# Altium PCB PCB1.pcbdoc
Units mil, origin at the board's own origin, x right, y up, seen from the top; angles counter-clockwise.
Board outline 17715 x 7065 mil, 4 copper layers (Top Layer, Inner1, Inner2, Bottom Layer); 91 components, 117 nets, 364 pads, 110 vias.
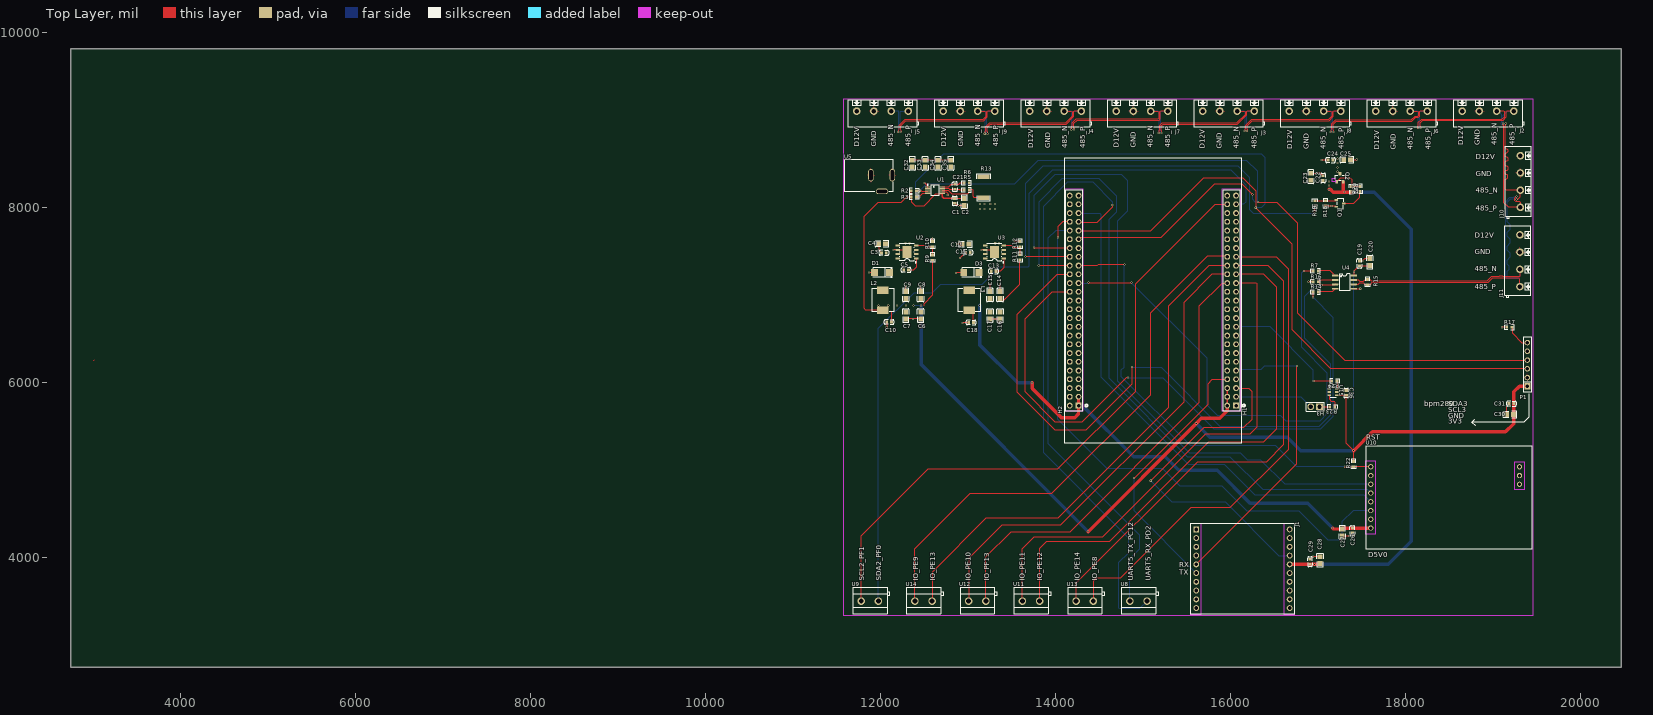
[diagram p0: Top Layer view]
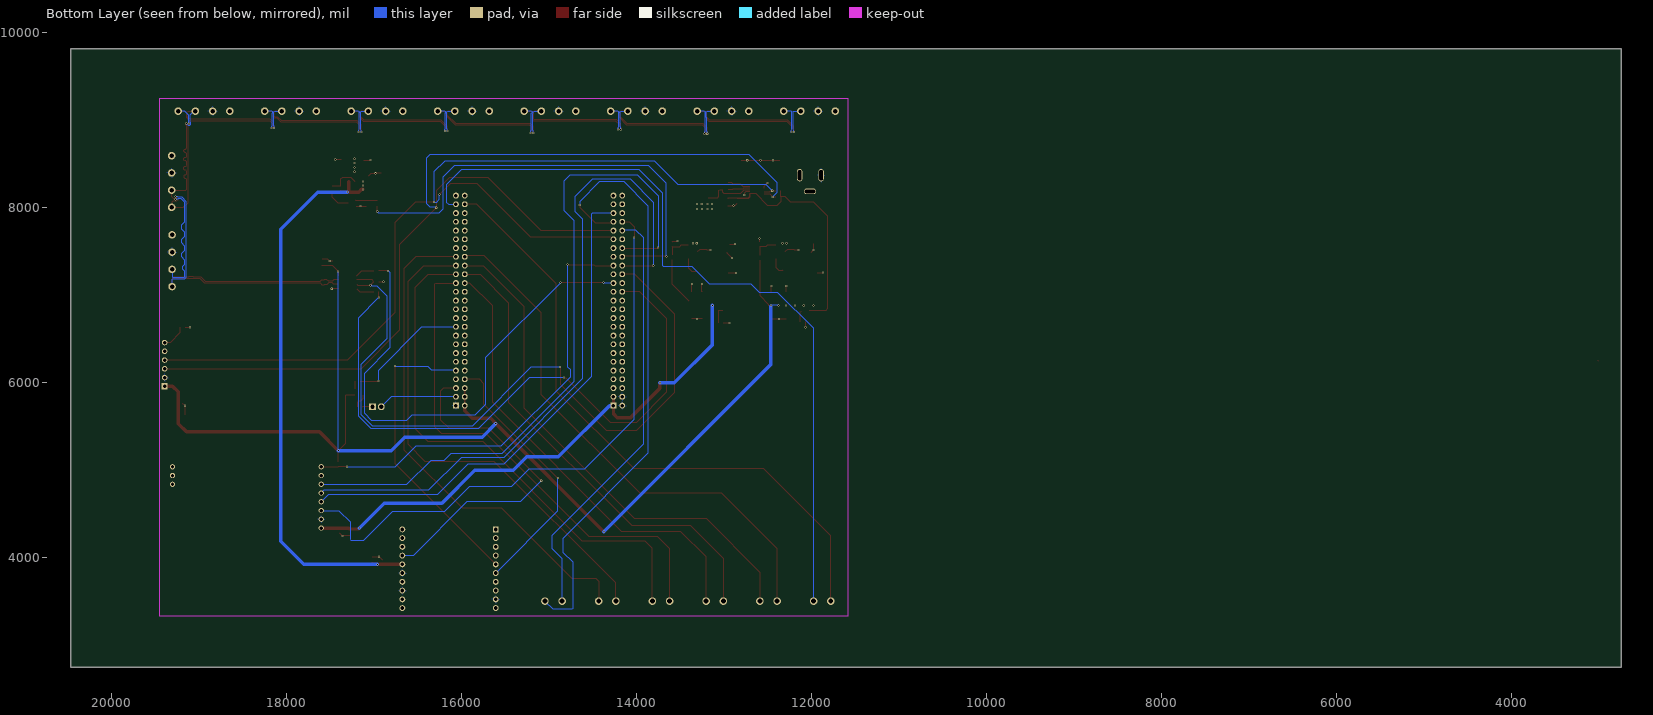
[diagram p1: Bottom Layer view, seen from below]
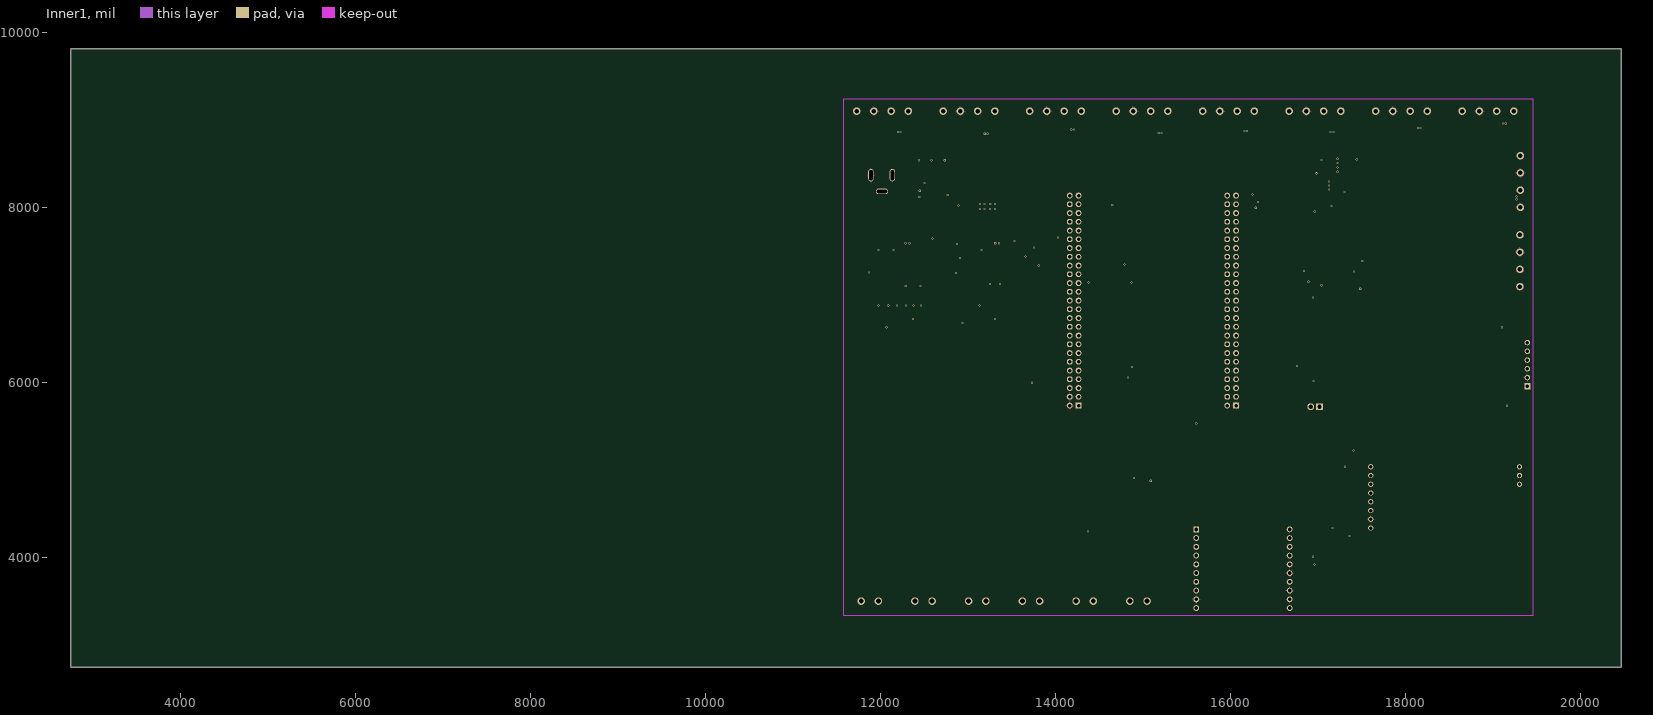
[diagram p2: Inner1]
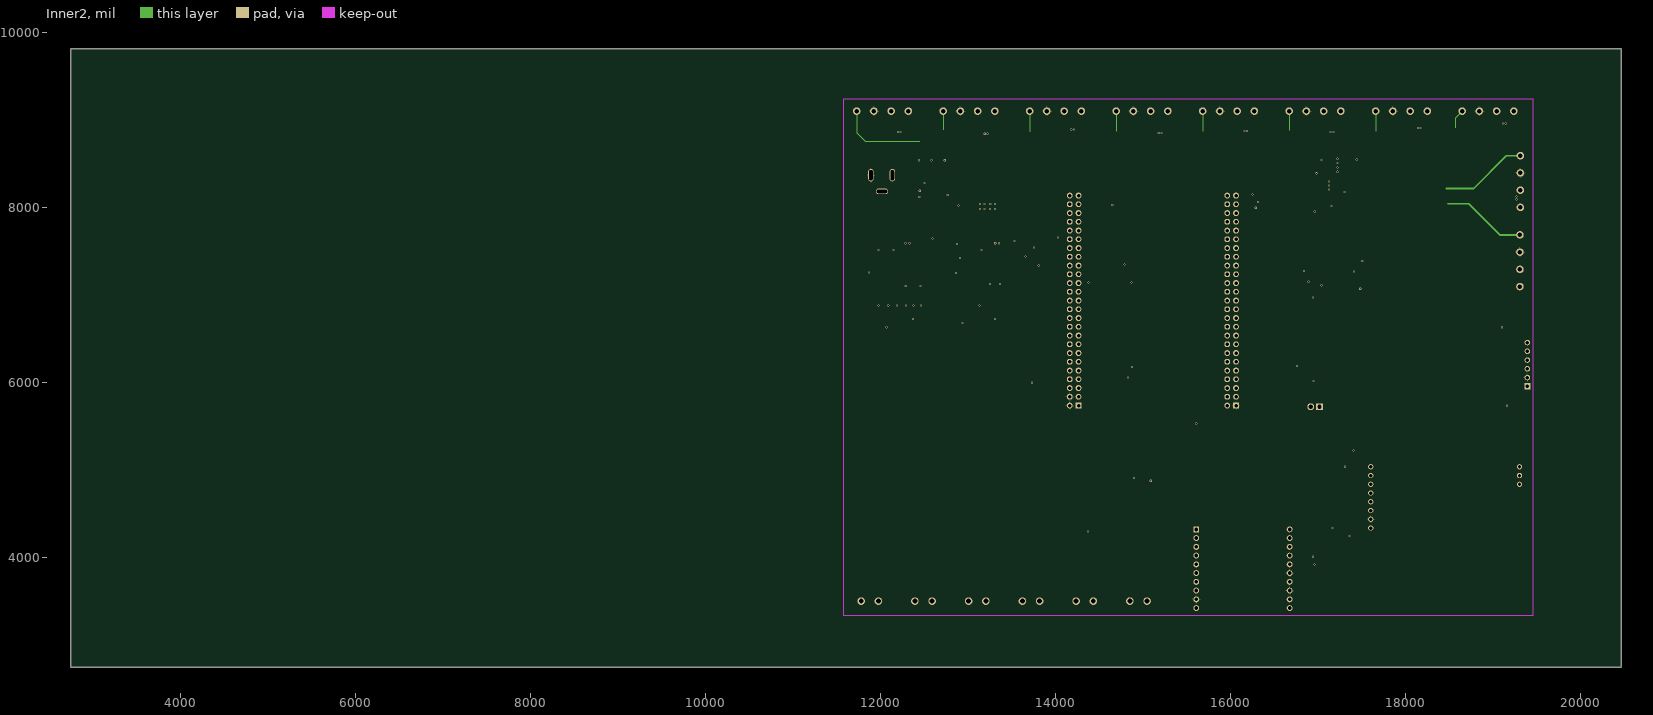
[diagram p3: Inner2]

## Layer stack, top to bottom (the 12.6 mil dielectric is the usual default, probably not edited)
Top Layer: signal copper (thickness not stored)
Dielectric: dielectric 12.6, FR-4, Dk 4.8
Inner1: signal copper (thickness not stored)
Dielectric: dielectric 12.6, FR-4, Dk 4.8
Inner2: signal copper (thickness not stored)
Dielectric: dielectric 12.6, FR-4, Dk 4.8
Bottom Layer: signal copper (thickness not stored)

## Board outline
20465,2750 2750,2750 2750,9815 20465,9815

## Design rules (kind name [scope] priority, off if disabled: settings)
BoardOutlineClearance copperThickness1oz [All] p0: genericclearance=10 ignorepadtopadclearanceinfootprint=FALSE except(0: Arc-SplitContinuation Track-SplitContinuation SMDPad-SplitContinuation THPad-SplitContinuation Via-SplitContinuation Fill-SplitContinuation Poly-SplitContinuation Region-SplitContinuation Text-SplitContinuation; 6: Track-CutoutEdge SMDPad-CutoutEdge THPad-CutoutEdge Via-CutoutEdge Region-CutoutEdge; 11.8: Track-OutlineEdge SMDPad-OutlineEdge THPad-OutlineEdge Via-OutlineEdge Fill-OutlineEdge Region-OutlineEdge Poly-OutlineEdge Text-OutlineEdge Fill-CutoutEdge)
BoardOutlineClearance copperThickness2oz [All] p0: genericclearance=10 ignorepadtopadclearanceinfootprint=FALSE except(0: Arc-SplitContinuation Track-SplitContinuation SMDPad-SplitContinuation THPad-SplitContinuation Via-SplitContinuation Fill-SplitContinuation Poly-SplitContinuation Region-SplitContinuation Text-SplitContinuation; 6: Track-CutoutEdge SMDPad-CutoutEdge THPad-CutoutEdge Via-CutoutEdge Region-CutoutEdge; 11.8: Track-OutlineEdge SMDPad-OutlineEdge THPad-OutlineEdge Via-OutlineEdge Fill-OutlineEdge Region-OutlineEdge Poly-OutlineEdge Text-OutlineEdge Fill-CutoutEdge)
Clearance copperThickness1oz [(InNet('D3V3') OR InNet('GND') OR InNet('D12V') OR InNet('$1N1879') OR InNet('$1N3397') OR InNet('$1N3226') OR InNet('$1N3388') OR InNet('D5V0') OR InNet('$1N488') OR InNet('$1N614') OR InNet('12VOUT') OR InNet('RESET') OR InNet('PA1') OR InNet('PC3') OR InNet('USART2_TX_PA2') OR InNet('USART2_RX_PA3') OR InNet('PC2') OR InNet('PA5') OR InNet('PA4') OR InNet('PC4') OR InNet('PA7') OR InNet('PB0') OR InNet('PC5') OR InNet('PB2') OR InNet('PB1') OR InNet('PF11') OR InNet('PF6') OR InNet('PF7') OR InNet('PB13') OR InNet('PB12') OR InNet('PD11') OR InNet('PF5') OR InNet('PD13') OR InNet('PD12') OR InNet('IO_PE11') OR InNet('IO_PF13') OR InNet('IO_PE12') OR InNet('IO_PE10') OR InNet('IO_PE14') OR InNet('IO_PE13') OR InNet('IO_PE8') OR InNet('IO_PE9') OR InNet('PD15') OR InNet('PE7') OR InNet('PD14') OR InNet('PE15') OR InNet('PD9') OR InNet('PD8') OR InNet('PF4') OR InNet('PD10') OR InNet('PF2') OR InNet('PF3') OR InNet('SDA2_PF0') OR InNet('SCL2_PF1') OR InNet('PB15') OR InNet('PF12') OR InNet('VBAT') OR InNet('PB4') OR InNet('PG14') OR InNet('PG13') OR InNet('PG12') OR InNet('PG11') OR InNet('PE3') OR InNet('PE2') OR InNet('PE5') OR InNet('PE6') OR InNet('PC0') OR InNet('PC1') OR InNet('PE1') OR InNet('PE0') OR InNet('PB7') OR InNet('PG10') OR InNet('PG9') OR InNet('PD5') OR InNet('PD4') OR InNet('PD3') OR InNet('PD1') OR InNet('PD0') OR InNet('PA15') OR InNet('USART3_TX_PB10') OR InNet('USART3_RX_PB11') OR InNet('PB3') OR InNet('PB5') OR InNet('EN_PB6') OR InNet('RST_PA6') OR InNet('AUX_PA12') OR InNet('PA11') OR InNet('EN_PG8') OR InNet('PG7') OR InNet('MD0_PG6') OR InNet('SDA3_PC9') OR InNet('PC8') OR InNet('SCL3_PA8') OR InNet('UART5_TX_PC12') OR InNet('UART5_RX_PD2') OR InNet('UART4_RX_PC11') OR InNet('UART4_TX_PC10') OR InNet('PG15') OR InNet('PD7') OR InNet('PD6') OR InNet('PC7') OR InNet('PC6') OR InNet('$1N7784') OR InNet('$1N8212') OR InNet('$1N8382') OR InNet('$1N8425') OR InNet('12VIN') OR InNet('$1N4237') OR InNet('$1N2426') OR InNet('$1N3228') OR InNet('$1N4276') OR InNet('485_1_N') OR InNet('485_1_P') OR InNet('TIM13_PF8') OR InNet('$1N39239') OR InNet('$1N39104') OR InNet('$1N39095'))] p1: gap=7 ignorepadtopadclearanceinfootprint=FALSE except(5.9: Track-Track; 6: Track-SMDPad SMDPad-SMDPad Track-THPad SMDPad-THPad THPad-THPad Track-Via SMDPad-Via THPad-Via Via-Via SMDPad-Fill THPad-Fill Via-Fill Fill-Fill Track-Region SMDPad-Region THPad-Region Via-Region Region-Region Track-Poly SMDPad-Poly THPad-Poly Via-Poly Fill-Poly Region-Poly Poly-Poly Track-Text SMDPad-Text THPad-Text Via-Text Fill-Text Region-Text Poly-Text Text-Text; 6.9: Track-Hole SMDPad-Hole THPad-Hole Via-Hole Fill-Hole Region-Hole Poly-Hole Text-Hole Sheet-Hole; 11.8: Track-Fill Fill-Region Track-Sheet SMDPad-Sheet THPad-Sheet Via-Sheet Fill-Sheet Region-Sheet Poly-Sheet Text-Sheet)
Clearance copperThickness2oz [All] p1: gap=7 ignorepadtopadclearanceinfootprint=FALSE except(6: Track-SMDPad SMDPad-SMDPad Track-THPad SMDPad-THPad THPad-THPad Track-Via SMDPad-Via THPad-Via Via-Via SMDPad-Fill THPad-Fill Via-Fill Fill-Fill Track-Region SMDPad-Region THPad-Region Via-Region Region-Region Track-Poly SMDPad-Poly THPad-Poly Via-Poly Fill-Poly Region-Poly Poly-Poly Track-Text SMDPad-Text THPad-Text Via-Text Fill-Text Region-Text Poly-Text Text-Text; 6.9: Track-Hole SMDPad-Hole THPad-Hole Via-Hole Fill-Hole Region-Hole Poly-Hole Text-Hole Sheet-Hole; 8: Track-Track; 11.8: Track-Fill Fill-Region Track-Sheet SMDPad-Sheet THPad-Sheet Via-Sheet Fill-Sheet Region-Sheet Poly-Sheet Text-Sheet)
DiffPairsRouting differentialPair [All] p1: maxuncoupledlength=10 minlimit=5.9843 maxlimit=5.9843 mostfreqgap=5.9843 toplayer_minwidth=5 toplayer_prefwidth=10 toplayer_maxwidth=100 bottomlayer_minwidth=5 bottomlayer_prefwidth=10 bottomlayer_maxwidth=100 midlayer1_minwidth=5 midlayer1_prefwidth=10 midlayer1_maxwidth=100 midlayer2_minwidth=5 midlayer2_prefwidth=10 midlayer2_maxwidth=100
PasteMaskExpansion pasteMaskExpansion [All] p1: expansion=0
PlaneConnect innerPlane [All] p1: planeconnectstyle=Relief reliefexpansion=20 reliefentries=4 reliefconductorwidth=10 reliefairgap=10
PolygonConnect copperRegion [All] p1: connectstyle=Direct reliefentries=4 reliefconductorwidth=10 polygonreliefangle="90 Angle" airgapwidth=10
RoutingVias viaSize [All] p1: viastyle="Through Hole" holewidth=12.0078 minholewidth=11.811 maxholewidth=248.0314 width=24.0158 minwidth=19.685 maxwidth=393.7008
SolderMaskExpansion solderMaskExpansion [All] p1: useseparateexpansions=TRUE expansion=2.0079 expansionbottom=2.0079
Width copperThickness1oz [All] p1: maxlimit=100 minlimit=5 preferedwidth=12
Width copperThickness2oz [All] p1: maxlimit=100 minlimit=8 preferedwidth=10

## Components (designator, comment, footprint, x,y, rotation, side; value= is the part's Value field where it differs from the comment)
C1 "CC0603KRX7R9BB104" C0603 12850,8080 r90 top
C2 "CL21A106KAYNNNE_C15850" C0805 12960,8065 r90 top
C3 "CC0603KRX7R9BB104" C0603 12040,7485 r0 top
C4 "CL21A106KAYNNNE_C15850" C0805 12020,7590 r0 top
C5 "0603B103K500NT" C0603 12295,7290 r0 top
C6 "CL21A106KAYNNNE_C15850" C0805 12460,6770 r270 top
C7 "CL21A106KAYNNNE_C15850" C0805 12290,6770 r270 top
C8 "CL21A106KAYNNNE_C15850" C0805 12460,7003.13 r90 top
C9 "CL21A106KAYNNNE_C15850" C0805 12290,7003.13 r90 top
C10 "CC0603KRX7R9BB104" C0603 12100,6695 r0 top
C11 "CC0603KRX7R9BB104" C0603 13000,7490 r0 top
C12 "CL21A106KAYNNNE_C15850" C0805 12975,7585 r0 top
C13 "0603B103K500NT" C0603 13295,7275 r0 top
C14 "CL21A106KAYNNNE_C15850" C0805 13368.29,7003.13 r90 top
C15 "CL21A106KAYNNNE_C15850" C0805 13252.64,7003.13 r90 top
C16 "CL21A106KAYNNNE_C15850" C0805 13368.29,6770 r270 top
C17 "CL21A106KAYNNNE_C15850" C0805 13252.64,6770 r270 top
C18 "CC0603KRX7R9BB104" C0603 13036.58,6688.76 r0 top
C19 "CC0603KRX7R9BB104" C0603 17475,7365 r270 top
C20 "CL21A106KAYNNNE_C15850" C0805 17595,7380 r270 top
C21 "CC0603KRX7R9BB104" C0603 12851.49,8241.02 r90 top
C22 "CC0603KRX7R9BB104" C0603 17060,8340 r90 top
C23 "CL21A106KAYNNNE_C15850" C0805 16920,8355 r90 top
C24 "CC0603KRX7R9BB104" C0603 17145,8545 r180 top
C25 "CL21A106KAYNNNE_C15850" C0805 17335,8550 r0 top
C26 "CC0603KRX7R9BB104" C0603 17395,4310 r90 top
C27 "CL21A106KAYNNNE_C15850" C0805 17280,4290 r90 top
C28 "CL21A106KAYNNNE_C15850" C0805 17024.79,3972.86 r270 top
C29 "CC0603KRX7R9BB104" C0603 16910,3955 r270 top
C30 "CL21A106KAYNNNE_C15850" C0805 19198.48,5637.1 r0 top
C31 "CC0603KRX7R9BB104" C0603 19213.48,5762.1 r0 top
C32 "CL21A106KAYNNNE_C15850" C0805 12364.68,8504.69 r90 top
C33 "CL21A106KAYNNNE_C15850" C0805 12511.45,8504.69 r90 top
C34 "CL21A106KAYNNNE_C15850" C0805 12658.23,8504.69 r90 top
C35 "CL21A106KAYNNNE_C15850" C0805 12805,8504.69 r90 top
C36 "CC0603KRX7R9BB104" C0603 17325,5885 r270 top
D1 "SS34_C8678" SMA_L4.3-W2.6-LS5.2-RD 12020,7260 r180 top
D3 "SS34_C8678" SMA_L4.3-W2.6-LS5.2-RD 13040,7260 r180 top
H1 "2.54-2*25P母" HDR-TH_50P-P2.54-V-F-R2-C25-S2.54-1 16015,6940 r90 top locked
H2 "2.54-2*25P母" HDR-TH_50P-P2.54-V-F-R2-C25-S2.54-1 14215,6940 r90 top locked
H3 "PZ254V-11-02P" HDR-TH_2P-P2.54-V-M 16969,5726.31 r180 top
J1 "EC800K核心板" HDR-TH_20P-P2.54-V-M-R2-C10-S2.54_HIF3H-20P-2.54W 15610,4325 r270 top
J2 "传感器端子" CONN-TH_4P-P5.00_KF301-5.0-4P 18945,9105 r180 top
J3 "传感器端子" CONN-TH_4P-P5.00_KF301-5.0-4P 15979.29,9105 r180 top
J4 "传感器端子" CONN-TH_4P-P5.00_KF301-5.0-4P 14002.14,9105 r180 top
J5 "传感器端子" CONN-TH_4P-P5.00_KF301-5.0-4P 12025,9105 r180 top
J6 "传感器端子" CONN-TH_4P-P5.00_KF301-5.0-4P 17956.43,9105 r180 top
J7 "传感器端子" CONN-TH_4P-P5.00_KF301-5.0-4P 14990.71,9105 r180 top
J8 "传感器端子" CONN-TH_4P-P5.00_KF301-5.0-4P 16967.86,9105 r180 top
J9 "传感器端子" CONN-TH_4P-P5.00_KF301-5.0-4P 13013.57,9105 r180 top
J10 "传感器端子" CONN-TH_4P-P5.00_KF301-5.0-4P 19315,8300 r90 top
J11 "传感器端子" CONN-TH_4P-P5.00_KF301-5.0-4P 19310,7395 r90 top
L2 "MWSA0603S-100MT" IND-SMD_L7.1-W6.6 12030,6945 r270 top
L3 "MWSA0603S-100MT" IND-SMD_L7.1-W6.6 13015,6945 r270 top
P1 "2.54-1*6P母" HDR-TH_6P-P2.54-V-F 19395,6210 r90 top
Q1 "S8050 J3Y(RANGE:200-350)" SOT-23-3_L3.0-W1.7-P0.95-LS2.9-BR 17255,8050 r180 top
Q2 "AO3401A_C15127" SOT-23_L2.9-W1.3-P1.90-LS2.4-BR 17252.93,8342.93 r270 top
R2 "0603WAF4701T5E" R0603 12382.84,8195 r180 top
R3 "0603WAF4701T5E" R0603 12382.84,8125 r180 top
R5 "0603WAF100JT5E" R0603 12985.34,8206.05 r0 top
R6 "0603WAF100JT5E" R0603 12985.34,8286.05 r0 top
R7 "0603WAF330JT5E" R0603 16975,7280 r0 top
R9 "0603WAF8201T5E" R0603 12595,7430 r90 top
R10 "0603WAF5101T5E" R0603 12595,7585 r90 top
R11 "0603WAF1202T5E" R0603 13595,7435 r90 top
R12 "0603WAF3901T5E" R0603 13595,7585 r90 top
R13 "JER2512F3R010" R2512 13180,8235 r270 top
R14 "0603WAF330JT5E" R0603 16975,7040 r0 top
R15 "0603WAF1200T5E" R0603 17570,7150 r90 top
R16 "0603WAF4701T5E" R0603 16975,7155 r0 top
R17 "0603WAF4701T5E" R0603 19190,6635 r0 top
R18 "0603WAF5101T5E" R0603 17090,8050 r90 top
R19 "0603WAF3901T5E" R0603 16965,8050 r270 top
R20 "0603WAF1004T5E" R0603 17480,8215 r90 top
R21 "0603WAF1004T5E" R0603 17385,8215 r270 top
R22 "0603WAF4701T5E" R0603 17410,5070 r90 top
R23 "0603WAF1200T5E" R0603 17165,5725 r180 top
R24 "0603WAF330JT5E" R0603 17190,6020 r180 top
U1 "INA226AIDGSR" MSOP-10_L3.0-W3.0-P0.50-LS5.0-BL 12625.34,8201.05 r270 top
U2 "TPS5430DDAR" ESOP-8_L4.9-W3.9-P1.27-LS6.0-TL-EP 12305,7495 r180 top
U3 "TPS5430DDAR" ESOP-8_L4.9-W3.9-P1.27-LS6.0-TL-EP 13305.01,7495 r180 top
U4 "SP3485EN-L/TR" SOIC-8_L5.0-W4.0-P1.27-LS6.0-BL 17305,7150 r270 top
U5 "XDJK-0051-025" DC-IN-TH_XDJK-0051-025 12015,8280 r0 top
U8 "KF301-5.0-2P" CONN-TH_P5.00_KF301-5.0-2P 14950,3505 r0 top
U9 "KF301-5.0-2P" CONN-TH_P5.00_KF301-5.0-2P 11879.47,3505 r0 top
U10 "LORA模块" LORA 17605,4340 r0 top
U11 "KF301-5.0-2P" CONN-TH_P5.00_KF301-5.0-2P 13721.79,3505 r0 top
U12 "KF301-5.0-2P" CONN-TH_P5.00_KF301-5.0-2P 13107.68,3505 r0 top
U13 "KF301-5.0-2P" CONN-TH_P5.00_KF301-5.0-2P 14335.89,3505 r0 top
U14 "KF301-5.0-2P" CONN-TH_P5.00_KF301-5.0-2P 12493.58,3505 r0 top
U15 "CN825S" SOT-23-6_L2.9-W1.6-P0.95-LS2.8-BL 17175,5895 r270 top

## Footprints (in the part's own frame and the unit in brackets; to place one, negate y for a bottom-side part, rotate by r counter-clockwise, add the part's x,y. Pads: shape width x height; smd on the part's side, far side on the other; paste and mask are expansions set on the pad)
C0603 [mm]
  rect 0.8x0.9 smd: 1(-0.7,0) 2(0.7,0)
  silkscreen extent -1.39,-0.71 1.39,0.71
C0805 [mm]
  rect 1.41x1.35 smd: 1(-1,0) 2(1,0)
  silkscreen extent -1.96,-0.9 1.96,0.9
CONN-TH_4P-P5.00_KF301-5.0-4P [mm]
  round 2.2 hole 1.3: 1(-7.5,0) 2(-2.5,0) 3(2.5,0) 4(7.5,0)
  silkscreen extent -10.58,-3.18 10.03,4.57
CONN-TH_P5.00_KF301-5.0-2P [mm]
  round 2.2 hole 1.4: 1(-2.5,0) 2(2.5,0)
  silkscreen extent -5,-3.7 5.71,4
DC-IN-TH_XDJK-0051-025 [mm]
  oval 1.6x3.6 hole 1 slot 3 at 90 deg: 1(3.1,2.35) 2(-3.1,2.35)
  oval 3.6x1.6 hole 1 slot 3 at 0 deg: 3(0.1,-2.35)
  silkscreen extent -10.8,-2.29 3.42,6.86
ESOP-8_L4.9-W3.9-P1.27-LS6.0-TL-EP [mm]
  rect 1.3x0.6 smd: 1(-2.7,1.905) 2(-2.7,0.635) 3(-2.7,-0.635) 4(-2.7,-1.905) 5(2.7,-1.905) 6(2.7,-0.635) 7(2.7,0.635) 8(2.7,1.905)
  rect 2.5x3.5 smd: 9(0,0)
  silkscreen extent -2.67,-2.55 2.05,3.2
HDR-TH_2P-P2.54-V-M [mm]
  rect 2x2 hole 1.2: 1(-1.27,0)
  round 2 hole 1.2: 2(1.27,0)
  silkscreen extent -2.54,-1.27 2.54,1.27
HDR-TH_6P-P2.54-V-F [mm]
  rect 1.8x1.8 hole 1.02: 1(-6.35,0)
  round 1.6 hole 1.02: 2(-3.81,0) 3(-1.27,0) 4(1.27,0) 5(3.81,0) 6(6.35,0)
  silkscreen extent -7.87,-1.25 7.87,1.25
HDR-TH_20P-P2.54-V-M-R2-C10-S2.54_HIF3H-20P-2.54W [mm]
  rect 1.7x1.7 hole 1.1: 1(0,0)
  round 1.7 hole 1.1: 2(2.54,0) 3(5.08,0) 4(7.62,0) 5(10.16,0) 6(12.7,0) 7(15.24,0) 8(17.78,0) 9(20.32,0) 10(22.86,0) 11(0,27.127) 12(2.54,27.127) 13(5.08,27.127) 14(7.62,27.127) 15(10.16,27.127) 16(12.7,27.127) 17(15.24,27.127) 18(17.78,27.127) 19(20.32,27.127) 20(22.86,27.127)
  silkscreen extent -1.77,-1.6 24.63,28.4
HDR-TH_50P-P2.54-V-F-R2-C25-S2.54-1 [mm]
  rect 1.7x1.7 hole 1.02: 1(-30.48,-1.27)
  round 1.7 hole 1.02: 2(-30.48,1.27) 3(-27.94,-1.27) 4(-27.94,1.27) 5(-25.4,-1.27) 6(-25.4,1.27) 7(-22.86,-1.27) 8(-22.86,1.27) 9(-20.32,-1.27) 10(-20.32,1.27) 11(-17.78,-1.27) 12(-17.78,1.27) 13(-15.24,-1.27) 14(-15.24,1.27) 15(-12.7,-1.27) 16(-12.7,1.27) 17(-10.16,-1.27) 18(-10.16,1.27) 19(-7.62,-1.27) 20(-7.62,1.27) 21(-5.08,-1.27) 22(-5.08,1.27) 23(-2.54,-1.27) 24(-2.54,1.27) 25(0,-1.27) 26(0,1.27) 27(2.54,-1.27) 28(2.54,1.27) 29(5.08,-1.27) 30(5.08,1.27) 31(7.62,-1.27) 32(7.62,1.27) 33(10.16,-1.27) 34(10.16,1.27) 35(12.7,-1.27) 36(12.7,1.27) 37(15.24,-1.27) 38(15.24,1.27) 39(17.78,-1.27) 40(17.78,1.27) 41(20.32,-1.27) 42(20.32,1.27) 43(22.86,-1.27) 44(22.86,1.27) 45(25.4,-1.27) 46(25.4,1.27) 47(27.94,-1.27) 48(27.94,1.27) 49(30.48,-1.27) 50(30.48,1.27)
  silkscreen extent -32,-3.92 32,2.54
IND-SMD_L7.1-W6.6 [mm]
  rect 2.15x3.32 smd: 1(-2.913,0) 2(2.913,0)
  silkscreen extent -3.3,-3.3 3.3,3.3
LORA [mil]
  round 60 hole 39.37: 1(0,0) 2(0,100) 3(0,200) 4(0,300) 5(0,400) 6(0,500) 7(0,600) 8(0,700) 9(1700,700) 10(1700,600) 11(1700,500)
  silkscreen extent -50,-241 1840,941
MSOP-10_L3.0-W3.0-P0.50-LS5.0-BL [mm]
  oval 0.28x1.62 smd: 1(-1,-2.11) 2(-0.5,-2.11) 3(0,-2.11) 4(0.5,-2.11) 5(1,-2.11) 6(1,2.11) 7(0.5,2.11) 8(0,2.11) 9(-0.5,2.11) 10(-1,2.11)
  silkscreen extent -1.74,-2.26 1.58,1.07
R0603 [mil]
  rect 31.75x34.02 smd: 1(-29.66,0) 2(29.66,0)
  silkscreen extent -55,-26 55,26
R2512 [mil]
  rect 50.49x136.06 smd: 1(-120.72,0) 2(120.72,0)
  silkscreen extent -155,-77 155,77
SMA_L4.3-W2.6-LS5.2-RD [mm]
  rect 2x2 smd: 1(-2.2,0) 2(2.2,0)
  silkscreen extent -2.98,-1.5 2.6,1.5
SOIC-8_L5.0-W4.0-P1.27-LS6.0-BL [mil]
  oval 22.38x76.78 smd: 1(-75,-106.5) 2(-25,-106.5) 3(25,-106.5) 4(75,-106.5) 5(75,106.5) 6(25,106.5) 7(-25,106.5) 8(-75,106.5)
  silkscreen extent -98,-59 98,59
SOT-23-3_L3.0-W1.7-P0.95-LS2.9-BR [mil]
  rect 40.85x20.95 smd: 1(43.36,-37.4) 2(43.36,37.4) 3(-43.36,0)
  silkscreen extent -34,-60 34,60
SOT-23-6_L2.9-W1.6-P0.95-LS2.8-BL [mil]
  rect 20.95x42.2 smd: 1(-37.4,-45.24) 2(0,-45.24) 3(37.4,-45.24) 4(37.4,45.24) 5(0,45.24) 6(-37.4,45.24)
  silkscreen extent -72,-57 61,35
SOT-23_L2.9-W1.3-P1.90-LS2.4-BR [mm]
  rect 1x0.8 smd: 1(1.15,-0.95) 2(1.15,0.95) 3(-1.15,0)
  silkscreen extent -0.7,-1.5 0.7,1.5

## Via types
v1: diameter 24.02, hole 12.01, Top Layer to Bottom Layer, 110 vias

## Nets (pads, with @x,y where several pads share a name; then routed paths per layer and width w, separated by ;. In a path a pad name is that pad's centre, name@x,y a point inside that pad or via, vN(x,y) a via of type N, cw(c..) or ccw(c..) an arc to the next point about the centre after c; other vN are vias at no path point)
12VIN: C32.1 C33.1 C34.1 C35.1 R6.2 R13.1 U5.1
12VOUT: C24.1 C25.1 J2.4 J3.4 J4.4 J5.4 J6.4 J7.4 J8.4 J9.4 Q2.3 | length 2594.5
  Inner2 w11.81: J5.4 11729.73,8855.27 11825,8760 12450,8760 ; J9.4 12718.3,8891.7 12720,8890 ; J4.4 13706.87,8873.13 13710,8870 ; 14695.44,8875 J7.4 ; 15684.01,8875 J3.4 ; 16672.58,8885 J8.4 ; 17661.15,8875 J6.4 ; 18570,8915 18570,9025.27 J2.4
  other v1: 17225.66,8411.52 17225.66,8462.84 17225.66,8513.5 17225.66,8560.74
485_1_N: J2.2 J3.2 J4.2 J5.2 J6.2 J7.2 J8.2 J9.2 J10.2 J11.2 R15.2 U4.7 | length 15853.1
  Top Layer w10: v1(12202.01,8865.98) 12202.01,8887.99 12209.02,8895 12209.02,8936.62 12278.38,9005.98 13168.41,9005.98 13202.43,9040 13202.43,9097.93 13195.36,9105 J9.2 ; v1(13193.31,8845.98) 13193.31,8867.99 13200.32,8875 13200.32,8920.32 13244.5,8964.5 14110.5,8964.5 14191,9045 14191,9097.93 14183.93,9105 J4.2 ; v1(14182.01,8895.98) 14182.01,8917.99 14189.02,8925 14189.02,8966.62 14235.32,9012.93 15172.5,9012.93 15179.57,9020 15179.57,9097.93 15172.5,9105 J7.2 ; v1(15182.01,8855.98) 15182.01,8877.99 15189.02,8885 15189.02,8936.62 15218.38,8965.98 16068.38,8965.98 16168.14,9065.75 16168.14,9097.93 16161.07,9105 J3.2 ; v1(16162.01,8875.98) 16162.01,8897.99 16169.02,8905 16169.02,8936.62 16238.38,9005.98 17117.7,9005.98 17156.72,9045 17156.72,9097.93 17149.64,9105 J8.2 ; v1(17147.01,8865.98) 17147.01,8887.99 17154.02,8895 17154.02,8956.62 17198.7,9001.3 18063.7,9001.3 18105.32,9042.93 18138.22,9042.93 18145.29,9050 18145.29,9097.93 18138.22,9105 J6.2 ; U4.7 17459.89,7175 17476.9,7157.99 17521.32,7157.99 17542.99,7179.66 R15.2 17597.01,7179.66 17618.68,7157.99 18932.99,7157.99 18984.68,7209.68 19070.21,7209.68 19075.52,7215 19111.29,7215 19116.61,7209.68 19302.93,7209.68 19310,7216.75 J11.2 ; v1(18143.31,8910.98) 18143.31,8932.99 18150.32,8940 18150.32,8975.32 18185.98,9010.98 19104.84,9010.98 19133.86,9040 19133.86,9097.93 19126.79,9105 J2.2 ; v1(19147.5,8965) 19147.5,8942.99 19140.49,8935.98 19140.49,8684.08 19140.92,8684.08 19155,8670 19165,8670 19175,8660 19175,8645 19160,8630 19155.49,8630 19140.49,8615 19140.49,8585.89 19151.38,8575 19165,8575 19175,8565 19175,8545 19165,8535 19151.34,8535 19140.49,8524.15 19140.49,8484.51 19150,8475 19165,8475 19175,8465 19175,8440 19165,8430 19150,8430 19140.49,8420.49 19140.49,8388.99 19152.71,8376.77 19163.23,8376.77 19170,8370 19170,8345 19159.3,8334.3 19151.13,8334.3 19140.49,8323.66 19140.49,8214.51 19153.42,8201.58 J10.2 19315,8125 19287.67,8097.67 v1(19269.02,8097.67)
  Bottom Layer w10: J5.2 12206.79,9105 12209.02,9102.77 12209.02,8895 12202.01,8887.99 v1(12202.01,8865.98) ; J9.2 13195.36,9105 13202.43,9097.93 13202.43,9033.73 13200.32,9031.62 13200.32,8875 13193.31,8867.99 v1(13193.31,8845.98) ; J4.2 14183.93,9105 14191,9097.93 14191,9087.93 14189.02,9085.94 14189.02,8925 14182.01,8917.99 v1(14182.01,8895.98) ; J7.2 15172.5,9105 15179.57,9097.93 15179.57,9081.31 15189.02,9071.86 15189.02,8885 15182.01,8877.99 v1(15182.01,8855.98) ; J3.2 16161.07,9105 16168.14,9097.93 16168.14,9081.31 16169.02,9080.44 16169.02,8905 16162.01,8897.99 v1(16162.01,8875.98) ; J8.2 17149.64,9105 17156.72,9097.93 17156.72,9087.93 17154.02,9085.23 17154.02,8895 17147.01,8887.99 v1(17147.01,8865.98) ; J6.2 18138.22,9105 18145.29,9097.93 18145.29,9081.31 18150.32,9076.28 18150.32,8940 18143.31,8932.99 v1(18143.31,8910.98) ; J2.2 19060,9105 19100,9065 19100,8980.02 19094.51,8974.52 19094.51,8955.48 19107.98,8942.01 19127.02,8942.01 19140.49,8955.48 19140.49,8957.99 v1(19147.5,8965) ; v1(19269.02,8097.67) 19247.01,8097.67 19240,8104.68 19202.29,8104.68 19162.93,8065.32 19162.93,7843 19200,7805.93 19200,7755 19162.93,7717.93 19162.93,7674.96 19200,7637.89 19200,7600 19162.93,7562.93 19162.93,7514.95 19200,7477.88 19200,7440 19162.93,7402.93 19162.93,7352.94 19185,7330.87 19185,7295.38 19162.93,7273.31 19162.93,7213.21 19170,7206.14 19302.93,7206.14 19310,7213.21 J11.2
485_1_P: J2.1 J3.1 J4.1 J5.1 J6.1 J7.1 J8.1 J9.1 J10.1 J11.1 R15.1 U4.6 | length 15863.5
  Top Layer w10: v1(12232.01,8865.98) 12232.01,8887.99 12225,8895 12225,8930 12285,8990 13175.03,8990 13218.41,9033.38 13218.41,9097.93 13225.48,9105 J9.1 ; v1(13223.31,8845.98) 13223.31,8867.99 13216.3,8875 13216.3,8913.7 13251.12,8948.52 14117.12,8948.52 14206.99,9038.38 14206.99,9097.93 14214.06,9105 J4.1 ; v1(14212.01,8895.98) 14212.01,8917.99 14205,8925 14205,8960 14241.94,8996.94 15179.12,8996.94 15195.56,9013.38 15195.56,9097.93 15202.63,9105 J7.1 ; v1(15212.01,8855.98) 15212.01,8877.99 15205,8885 15205,8930 15225,8950 16075,8950 16184.13,9059.13 16184.13,9097.93 16191.2,9105 J3.1 ; v1(16192.01,8875.98) 16192.01,8897.99 16185,8905 16185,8930 16245,8990 17124.32,8990 17172.7,9038.38 17172.7,9097.93 17179.77,9105 J8.1 ; v1(17177.01,8865.98) 17177.01,8887.99 17170,8895 17170,8950 17205.32,8985.32 18070.32,8985.32 18111.94,9026.94 18144.84,9026.94 18161.27,9043.38 18161.27,9097.93 18168.34,9105 J6.1 ; U4.6 17459.89,7125 17476.9,7142.01 17521.32,7142.01 17542.99,7120.34 R15.1 17597.01,7120.34 17618.68,7142.01 18939.61,7142.01 18991.3,7193.7 19299.39,7193.7 19310,7183.09 J11.1 ; v1(18173.31,8910.98) 18173.31,8932.99 18166.3,8940 18166.3,8968.7 18192.61,8995 19111.46,8995 19149.84,9033.38 19149.84,9097.93 19156.91,9105 J2.1 ; v1(19117.5,8965) 19117.5,8942.99 19124.51,8935.98 19124.51,8060.49 19180.28,8004.73 J10.1 19315,8061.28 19301.59,8074.68 19259.49,8074.68 19246.02,8088.15 19246.02,8107.2 19259.49,8120.67 19269.02,8120.67 v1(19269.02,8127.67)
  Bottom Layer w10: v1(12232.01,8865.98) 12232.01,8887.99 12225,8895 12225,9095 12232.07,9102.07 12233.98,9102.07 12236.91,9105 J5.1 ; v1(13223.31,8845.98) 13223.31,8867.99 13216.3,8875 13216.3,9025 13218.41,9027.11 13218.41,9097.93 13225.48,9105 J9.1 ; v1(14212.01,8895.98) 14212.01,8917.99 14205,8925 14205,9079.32 14206.99,9081.31 14206.99,9097.93 14214.06,9105 J4.1 ; v1(15212.01,8855.98) 15212.01,8877.99 15205,8885 15205,9078.49 15195.56,9087.93 15195.56,9097.93 15202.63,9105 J7.1 ; v1(16192.01,8875.98) 16192.01,8897.99 16185,8905 16185,9087.06 16184.13,9087.93 16184.13,9097.93 16191.2,9105 J3.1 ; v1(17177.01,8865.98) 17177.01,8887.99 17170,8895 17170,9078.61 17172.7,9081.31 17172.7,9097.93 17179.77,9105 J8.1 ; v1(18173.31,8910.98) 18173.31,8932.99 18166.3,8940 18166.3,9082.9 18161.27,9087.93 18161.27,9097.93 18168.34,9105 J6.1 ; v1(19117.5,8965) 19117.5,9057.5 19165,9105 J2.1 ; v1(19269.02,8127.67) 19247.01,8127.67 19240,8120.67 19195.67,8120.67 19146.94,8071.94 19146.94,7206.59 19163.38,7190.16 19302.93,7190.16 19310,7183.09 J11.1
$1N488: C21.2 R6.1 U1.10 | length 266.2
  Top Layer w10: U1.10 12780.42,8240.42 12808.58,8268.58 C21.2 12898.58,8268.58 12916.05,8286.05 R6.1
$1N614: C21.1 R5.1 U1.9 | length 254.2
  Top Layer w10: U1.9 12779.27,8220.73 12786.54,8213.46 C21.1 12901.54,8213.46 12910,8205 12954.64,8205 R5.1
$1N1879: C5.2 U2.1 | length 204.5
  Top Layer w10: C5.2 12327.56,7285 12375,7285 12411.3,7321.3 U2.1
$1N2426: R9.2 R10.1 U2.4 | length 285.7
  Top Layer w10: U2.4 12510,7570 12525,7555 12594.66,7555 R10.1 R9.2
$1N3226: C13.2 U3.1 | length 209.5
  Top Layer w10: C13.2 13370,7275 13411.31,7316.31 U3.1
$1N3228: R11.2 R12.1 U3.4 | length 284.9
  Top Layer w10: U3.4 13495,7570 13515,7550 13589.66,7550 R12.1 R11.2
$1N3388: C13.1 D3.1 L3.1 U3.8
$1N3397: C5.1 D1.1 L2.1 U2.8
$1N4237: R7.2 U4.1 | length 216.6
  Top Layer w10: R7.2 17143.5,7280 U4.1
$1N4276: R14.2 U4.4 | length 208.3
  Top Layer w10: R14.2 17163.5,7040 U4.4
$1N7784: P1.6 R17.2 | length 285.7
  Top Layer w11.81: R17.2 19219.66,6570.34 19330,6460 P1.6
$1N8212: Q1.1 R18.2 R19.1 | length 249.8
  Top Layer w10: R19.1 R18.2 17203.9,8079.66 Q1.1
$1N8382: Q1.3 R20.1 | length 276
  Top Layer w11.81: Q1.3 17410,8050 17480,8120 R20.1
$1N8425: Q2.1 R20.2 R21.1 | length 372.7
  Top Layer w7.87: Q2.1 17262.87,8345 17365,8345 17385,8325 R21.1
  Top Layer w11.81: R21.1 R20.2
$1N39095: R24.1 U15.6 | length 87.8
  Top Layer w11.81: R24.1 17220.24,6019.42 U15.6
$1N39104: R23.1 U15.3 | length 177.2
  Top Layer w11.81: U15.3 17129.76,5815.24 17155,5790 17185,5790 17194.86,5780.14 17194.86,5725.2 R23.1
$1N39239: H3.1 R23.2 | length 119
  Top Layer w11.81: H3.1 17129.03,5726.31 R23.2@17135.34,5720
AUX_PA12: H2.34 U10.5 | length 7810.5
  Top Layer w11.81: v1(13810,7340) H2.34
  Bottom Layer w11.81: v1(13810,7340) 13810,8065.05 14074.95,8330 14500,8330 14700,8130 14700,7956.18 14615,7871.18 14615,6050 15515,5150 16000,5150 16375,4775 17570,4775 U10.5
D3V3: C1.2 C2.2 C6.1 C7.1 C8.1 C9.1 C10.2 C19.2 C20.2 C30.2 C31.2 C36.2 H1.2 H1.4 H1.6 L2.2 P1.1 R2.2 R3.2 R9.1 R22.2 U1.6 U4.8 U15.4 | length 16958.8
  Top Layer w10: 12495,6880 12495,6900 12595,7000 R9.1
  Top Layer w11.81: L2.2 11834.68,6830.32 11815,6850 11815,7905 11975,8065 12240,8065 12300,8125 R3.2 ; 12120,6820 12127.56,6812.44 C10.2 ; R2.2 R3.2 ; U1.6 12706.74,8160 12635,8160 12500,8025 12400,8025 12353.18,8071.82 R3.2 ; C1.2 12956.81,8107.56 C2.2 ; U15.4 17324.84,5857.6 C36.2 17325,5310 v1(17410,5225) R22.2 ; U4.8 v1(17411.5,7273.94) C19.2 17591.81,7337.44 C20.2
  Top Layer w15.75: U1.6 12708.41,8125 12725.85,8107.56 C1.2
  Top Layer w19.68: H1.2 H1.4 H1.6
  Top Layer w39.37: v1(14375,4300) v1(15610,5535) 15670,5595 15880,5595 15965,5680 H1.2 ; v1(17410,5225) 17625,5440 19145,5440 19237.85,5532.85 C30.2 19241.04,5640.29 C31.2 19241.04,5896.04 19305,5960 P1.1
  Bottom Layer w11.81: v1(12378.02,6885) v1(12465,6885) ; v1(17410,5225) 17410,7272.44 v1(17411.5,7273.94)
  Bottom Layer w39.37: v1@12465,6874.25 12465,6210 v1(14375,4300) ; v1(15610,5535) 15765,5380 16650,5380 16805,5225 v1(17410,5225)
  other v1: 11979.28,6885 12090.76,6885 12190.44,6885 12291.9,6885
D5V0: C14.1 C15.1 C16.1 C17.1 C18.2 C26.2 C27.2 H2.1 H2.3 L3.2 R11.1 U10.1 | length 6854.4
  Top Layer w10: 13400,6930 13595,7125 R11.1
  Top Layer w11.81: L3.2 13064.14,6830.32 C18.2
  Top Layer w39.37: v1(13735,6000) 13735,5935 14070,5600 14220,5600 14265,5645 H2.1 H2.3 ; v1(17170,4340) 17180.63,4329.37 C27.2 17288.19,4337.56 C26.2 17397.44,4340 U10.1
  Bottom Layer w39.37: v1(13133.74,6885) 13133.74,6435 13568.74,6000 v1(13735,6000) ; H2.1 14310,5740 14895,5155 15255,5155 15410,5000 15850,5000 16225,4625 16885,4625 v1(17170,4340)
D12V: C3.2 C4.2 C11.2 C12.2 C22.1 C23.1 C28.2 C29.2 J1.15 J10.4 J11.4 Q2.2 R5.2 R13.2 R21.2 U1.8 U2.7 U3.7 | length 9045.2
  Top Layer w10: U1.8 12773.95,8201.05 12815,8160 13000,8160 13015,8175 R5.2 13016.03,8207.07 13052.93,8207.07 13060,8200 13060,8130 13075.72,8114.28 R13.2
  Top Layer w39.37: J1.15 v1(16963,3925) 17011.3,3925 17019.79,3933.49 C28.2 ; v1(17130,8210.88) 17145,8210.88 17175.88,8180 v1(17305,8180) ; Q2.2 17290.33,8194.67 v1(17305,8180) ; R21.2 17379.66,8180 v1(17305,8180)
  Inner2 w19.68: 18470,8220 18780,8220 19155.28,8595.27 J10.4 ; 18485,8045 18725.91,8045 19080.91,7690 19309.72,7690 J11.4
  Bottom Layer w39.37: v1(16963,3925) 17805,3925 18070,4190 18070,7755 17645,8180 v1(17305,8180)
  other v1: 13140,7985 13191.06,7985 13253.59,7985 13308.44,7985 13140,8045 13189.86,8045 13256.2,8045 13308.42,8045 17130,8256.58 17130,8300
EN_PB6: H2.32 R16.2 U4.2 U4.3 | length 8331.9
  Top Layer w10: v1(17040,7115) v1@17044.66,7115 ; U4.3 17188.5,7115 v1@17044.66,7115 ; U4.2 17024.66,7175 R16.2 v1@17044.66,7115
  Top Layer w11.81: H2.32 14020,7240 13565,6785 13565,5890 14000,5455 14345,5455 14875,5985 v1(14875,6180)
  Bottom Layer w10: v1(14875,6180) 14880,6175 15210,6175 15880,5505 17015,5505 17145,5635 17145,6213.97 16850,6508.97 16850,6990 16962.07,7102.07 17022.07,7102.07 17035,7115 v1(17040,7115)
EN_PG8: H2.36 R19.2 | length 5236
  Top Layer w10: v1(16965,7960) R19.2
  Top Layer w11.81: v1(13660,7445) 14160,7445 H2.36
  Bottom Layer w11.81: v1(13660,7445) 13660,8280 13860,8480 16085,8480 16215,8350 16215,7985 16260,7940 16945,7940 v1(16965,7960)
GND: C1.1 C2.1 C3.1 C4.1 C6.2 C7.2 C8.2 C9.2 C10.1 C11.1 C12.1 C14.2 C15.2 C16.2 C17.2 C18.1 C19.1 C20.1 C22.2 C23.2 C24.2 C25.2 C26.1 C27.1 C28.1 C29.1 C30.1 C31.1 C32.2 C33.2 C34.2 C35.2 C36.1 D1.2 D3.2 H1.1 H2.2 H2.4 J1.9 J1.16 J1.18 J2.3 J3.3 J4.3 J5.3 J6.3 J7.3 J8.3 J9.3 J10.3 J11.3 P1.2 Q1.2 R10.2 R12.2 R16.1 R17.1 R18.1 U1.1 U1.2 U1.7 U2.6 U2.9 U3.6 U3.9 U4.5 U5.2 U10.2 U15.2 | length 3413.5
  Top Layer w10: v1(12150,7520) U2.6 12280,7520 U2.9 ; v1(13155,7520) U3.6 13280,7520 U3.9 ; C23.2 v1(16985,8394.37) 17033.19,8394.37 C22.2
  Top Layer w11.81: v1(11870,7260) D1.2 ; C4.1 v1(11980.63,7516.81) C3.1 ; v1(12072.44,6635) C10.1 ; C7.2 v1(12371.47,6730.63) C6.2 ; C9.2 v1(12290,7105) ; C32.2 v1(12441.49,8544.06) C33.2 v1(12583.05,8544.06) C34.2 v1(12736.12,8544.06) C35.2 ; C8.2 v1(12460,7105) ; v1(12505,8285) 12542.27,8247.73 U1.1 U1.2 ; R10.2 v1(12595,7650) ; U1.7 12753.64,8181.36 12770,8165 v1(12770,8145) ; C1.1 12876.81,8025.63 v1(12894.52,8025.63) C2.1 ; v1(12865,7255) 12948.39,7255 D3.2 ; v1(12875,7585) C12.1 ; v1(12910,7425) 12972.44,7487.44 C11.1 ; v1(12940,6685) 13005.26,6685 C18.1 ; C17.2 v1(13311.1,6730.63) C16.2 ; C15.2 13253.5,7043.36 v1(13253.5,7130.49) ; C14.2 v1(13368.29,7130.49) ; v1(13535,7620) 13589.66,7620 R12.2 ; v1(16895,7155) R16.1 ; C29.1@16910,3977.56 v1(16944.67,4012.23) C28.1 ; v1(17040,8545) C24.2 ; R18.1 v1(17154.66,8020.34) 17199.66,8020.34 Q1.2@17204.66,8015.34 ; C27.1 v1(17363.19,4250.63) C26.1 ; C25.2 v1(17445,8550) ; U4.5 v1(17485,7075) ; C19.1 v1(17507.56,7392.56) 17534.37,7419.37 C20.1 ; v1(19105,6635) R17.1 ; C30.1 19159.11,5735.29 C31.1
  other v1: 19162.33,5737.74 12285.51,7595.39 12335.45,7595.39 13313.08,7595.39 13356.15,7595.39
IO_PE8: H1.35 U13.2 | length 5794.6
  Top Layer w11.81: U13.2 14434.32,3729.32 14470,3765 14740,3765 15545,4570 15995,4570 16660,5235 16660,7305 16525,7440 H1.35
IO_PE9: H1.36 U14.1 | length 6107.3
  Top Layer w11.81: U14.1 12395.15,4105.15 13025,4735 13960,4735 15090,5865 15090,6800 15740,7450 15955,7450 H1.36
IO_PE10: H1.32 U12.1 | length 5454.3
  Top Layer w11.81: U12.1 13009.26,3994.26 13385,4370 14055,4370 15465,5780 15465,6915 15790,7240 H1.32
IO_PE11: H1.29 U11.1 | length 5736.5
  Top Layer w11.81: U11.1 13623.36,4103.36 13760,4240 14540,4240 15720,5420 16230,5420 16305,5495 16305,7131.65 16296.65,7140 H1.29
IO_PE12: H1.31 U11.2 | length 6022.4
  Top Layer w11.81: U11.2 13820.21,4110.21 13900,4190 14620,4190 15755,5325 16380,5325 16530,5475 16530,7090 16380,7240 H1.31
IO_PE13: H1.34 U14.2 | length 5835.5
  Top Layer w11.81: U14.2 12592,3837 13205,4450 14025,4450 15290,5715 15290,6875 15755,7340 H1.34
IO_PE14: H1.33 U13.1 | length 5720.1
  Top Layer w11.81: U13.1 14237.47,3712.47 15625,5100 16415,5100 16610,5295 16610,7160 16435,7335 16070,7335 H1.33
IO_PF13: H1.30 U12.2 | length 5208.3
  Top Layer w11.81: U12.2 13206.11,4011.11 13495,4300 14170,4300 15645,5775 15645,6880 15905,7140 H1.30
MD0_PG6: H2.38 U10.6 | length 7926.9
  Top Layer w11.81: v1(13755,7545) 13760,7540 H2.38
  Bottom Layer w11.81: v1(13755,7545) 13755,8140 13995,8380 14760,8380 14830,8310 14830,7965 14715,7850 14715,6020 15538.02,5196.98 16116.82,5196.98 16198.8,5115 16350,5115 16625,4840 U10.6
PA1: H1.5 J1.14 | length 3906.6
  Top Layer w11.81: v1(15090,4880) 15695,5485 16150,5485 16245,5580 16245,5905 16210,5940 H1.5
  Bottom Layer w10: v1(15090,4880) 15330,4640 15940,4640 16555,4025 J1.14
PA4: H1.12
PA5: H1.11
PA7: H1.14
PA11: H2.35
PA15: H2.27
PB0: H1.15
PB1: H1.18
PB2: H1.17
PB3: H2.30
PB4: H2.6
PB5: H2.31
PB7: H2.19
PB12: H1.24
PB13: H1.23
PB15: H1.49
PC0: H2.15
PC1: H2.16
PC2: H1.10
PC3: H1.7
PC4: H1.13
PC5: H1.16
PC6: H2.50
PC7: H2.49
PC8: H2.40
PD0: H2.26
PD1: H2.25
PD3: H2.24
PD4: H2.23
PD5: H2.22
PD6: H2.48
PD7: H2.47
PD8: H1.42
PD9: H1.41
PD10: H1.44
PD11: H1.25
PD12: H1.28
PD13: H1.27
PD14: H1.39
PD15: H1.37
PE0: H2.18
PE1: H2.17
PE2: H2.12
PE3: H2.11
PE5: H2.13
PE6: H2.14
PE7: H1.38
PE15: H1.40
PF2: H1.45
PF3: H1.46
PF4: H1.43
PF5: H1.26
PF6: H1.21
PF7: H1.22
PF11: H1.20
PF12: H1.50
PG7: H2.37
PG9: H2.21
PG10: H2.20
PG11: H2.10
PG12: H2.9
PG13: H2.8
PG14: H2.7
PG15: H2.46
RESET: H1.3 H3.2 | length 901.1
  Bottom Layer w11.81: H1.3 16805.31,5840 H3.2
RST_PA6: H2.33 R22.1 U10.8 | length 5104.9
  Top Layer w10: R22.1 17410.34,5040 U10.8
  Top Layer w11.81: H2.33 14270,7335 14475,7335 14490,7350 v1(14790,7350) ; v1(17310,5040) R22.1@17410.34,5040
  Bottom Layer w11.81: v1(14790,7350) 14785,7345 14785,6180 14755,6150 14755,6070 15545,5280 16520,5280 16760,5040 v1(17310,5040)
SCL2_PF1: H1.48 U9.1 | length 7217
  Top Layer w11.81: U9.1 11781.05,4251.05 12545,5015 14030,5015 14920,5905 14920,7130 15830,8040 H1.48
SCL3_PA8: H2.41 P1.3 R3.1 U1.5 | length 12104.8
  Top Layer w10: R3.1 12443.32,8125 12480,8161.68 U1.5 ; v1(16290,8001.19) 16705,7586.19 16705,6605 17150,6160 P1.3
  Top Layer w11.81: H2.41 15090,7740 15695,8345 16140,8345 16290,8195 v1(16290,8001.19)
  Bottom Layer w11.81: v1(12445,8125) 12400,8170 12400,8290 12720,8610 16360,8610 16400,8570 16400,8045 16360,8005 16293.81,8005 v1(16290,8001.19)
SDA2_PF0: H1.47 U9.2 | length 8941.5
  Bottom Layer w11.81: U9.2 11977.9,6622.9 12385,7030 12595,7030 12689.6,7124.6 13164.6,7124.6 13365,7325 13688.19,7325 13700,7336.81 13700,8165 13970,8435 16005,8435 16175,8265 16175,8065 16150,8040 H1.47
SDA3_PC9: H2.39 P1.4 R2.1 U1.4 | length 11407.2
  Top Layer w10: R2.1 v1(12450,8195) 12465,8195 12478.64,8181.36 U1.4 ; v1(16315,8066.19) 16528.81,8066.19 16765,7830 16765,6800 17305,6260 P1.4
  Top Layer w11.81: H2.39 14290,7665 15210,7665 15820,8275 16130,8275 v1(16255,8150)
  Bottom Layer w10: v1(12450,8195) 12525,8270 13530,8270 13800,8540 16190,8540 16315,8415 v1(16315,8066.19)
  Bottom Layer w11.81: v1(16255,8150) 16255,8095 16283.81,8066.19 v1(16315,8066.19)
TIM13_PF8: H1.19 R24.2 | length 1425.4
  Top Layer w11.81: v1(16950,6020) R24.2
  Bottom Layer w11.81: H1.19 16455,6640 16950,6145 v1(16950,6020)
UART4_RX_PC11: H2.44 U10.3 | length 6763.1
  Top Layer w11.81: v1(14030,7660) 14030,7785 14085,7840 H2.44
  Bottom Layer w11.81: v1(14030,7660) 14030,5585 14595,5020 15225,5020 15430,4815 15910,4815 16195,4530 16790,4530 17118.35,4201.65 17266.65,4201.65 17275,4210 17275,4410 17405,4540 U10.3
UART4_TX_PC10: H2.45 U10.4 | length 5795.4
  Bottom Layer w11.81: H2.45 14508.19,7940 14520,7928.19 14520,6070 15520,5070 15930,5070 16277.72,4722.28 17522.72,4722.28 U10.4
UART5_RX_PD2: H2.43 U8.2 | length 6928.7
  Top Layer w11.81: H2.43 14275,7830 14475,7830 14650,8005 v1(14650,8030)
  Bottom Layer w11.81: v1(14650,8030) 14650,8070 14425,8295 14140,8295 13865,8020 13865,5200 14840,4225 14840,4060 14726.65,3946.65 14726.65,3423.35 14735,3415 14958.42,3415 U8.2
UART5_TX_PC12: H2.42 U8.1 | length 4914.2
  Bottom Layer w11.81: H2.42 14160,7745 14010,7745 13920,7655 13920,5305 14965,4260 14965,4105 14851.58,3991.57 U8.1
USART2_RX_PA3: H1.9 J1.5 | length 3457.1
  Top Layer w11.81: J1.5 16760,5075 v1(16760,6190)
  Bottom Layer w11.81: H1.9 16075,6150 16345,6150 16385,6190 v1(16760,6190)
USART2_TX_PA2: H1.8 J1.6 | length 3049.8
  Top Layer w11.81: v1(14900,4910) 15745,5755 15745,5990 15795,6040 H1.8
  Bottom Layer w11.81: v1(14900,4910) 14900,4535 J1.6
USART3_RX_PB11: H2.29 R7.1 | length 5718
  Top Layer w10: v1(16840,7280) R7.1
  Top Layer w11.81: v1(14380,7145) v1(14870,7145)
  Bottom Layer w11.81: H2.29 14375,7140 v1(14380,7145) ; v1(14870,7145) 15730,6285 15730,5750 15850,5630 16570,5630 16635,5565 17025,5565 17110,5650 17110,6110.26 16815,6405.26 16815,7255 v1(16840,7280)
USART3_TX_PB10: H2.28 R14.1 | length 7169
  Top Layer w10: v1(16945,6975) 16945.34,6975.34 R14.1
  Top Layer w11.81: H2.28 13965,7040 13655,6730 13655,5895 14000,5550 14303.3,5550 14813.3,6060 v1(14830,6060)
  Bottom Layer w10: v1(14830,6060) 15225,6060 15810.83,5474.17 17034.17,5474.17 17175,5615 17175,6745 v1(16945,6975)
VBAT: H2.5
pads on no net: J1.1 J1.2 J1.3 J1.4 J1.7 J1.8 J1.10 J1.11 J1.12 J1.13 J1.17 J1.19 J1.20 P1.5 U1.3 U2.2 U2.3 U2.5 U3.2 U3.3 U3.5 U5.3 U10.7 U10.9 U10.10 U10.11 U15.1 U15.5
copper on no net: | length 14.1
  Top Layer w10: 3005,6250 3015,6260

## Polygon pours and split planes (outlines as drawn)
12VIN on Top Layer (solid, remove dead copper, pour order 0): 12070.23,8355.54 12070.23,8445 12130.23,8505 13215,8505 13295,8425 13295,8270 13285,8260 13011.39,8260 12985.34,8286.05 12985.34,8324.66 12980,8330 12095.77,8330
D12V on Inner2 (solid, remove dead copper): 17105,8360 18580,8360 18655,8285 18655,7910 18635,7890 18630,7885 17432.47,7885 17106.6,8210.88 17106.6,8358.4
12VOUT on Inner2 (solid, remove dead copper): 12415,8965 12320,8870 12320,8715 12607.61,8427.39 18655,8427.39 18655,8965
$1N3388 on Top Layer (solid, remove dead copper, pour order 2): 13055,7435 13211.5,7435 13242.86,7403.64 13242.86,7398.54 13280,7361.39 13280,7200 13144.92,7064.92 13144.92,6993.31 12950.49,6993.31 12892.83,7050.97 12892.83,7122.83 12910,7140 13000,7140 13020,7160 13020,7400
$1N3397 on Top Layer (solid, remove dead copper, pour order 4): 12054.99,7435 12211.49,7435 12242.85,7403.64 12242.85,7398.54 12279.99,7361.39 12279.99,7200 12144.91,7064.92 12144.91,6978.31 11965.48,6978.31 11892.82,7050.97 11892.82,7122.83 11909.99,7140 11999.99,7140 12019.99,7160 12019.99,7400
D3V3 on Top Layer (solid, remove dead copper, pour order 6): 11921.56,6815 11921.56,6905.44 11971.11,6955 12520,6955 12550,6925 12550,6815 12530,6795 11941.56,6795
D5V0 on Top Layer (solid, remove dead copper, pour order 8): 12885,6880 12981.36,6976.36 13388.64,6976.36 13440,6925 13440,6805 13438.87,6805 13419.66,6785.8 12896.28,6785.8 12885,6797.07
D12V on Top Layer (solid, remove dead copper, pour order 10): 13105,8160 13105,7935 13100,7930 12090,7930 12035,7875 12035,7488.83 12066.78,7457.05 12222.95,7457.05 12225,7455 12225,7475.55 12209.64,7490.91 12144.09,7490.91 12130,7505 12130,7600 12250,7720 12915,7720 12975,7660 12975,7542.94 13000,7517.94 13000,7463.61 13011.03,7452.58 13210.96,7452.58 13224.01,7465.62 13224.01,7471.72 13203.34,7492.39 13132.61,7492.39 13105,7520 13105,7605 13225,7725 13335,7725 13335,8158.62 13333.62,8160
D12V on Top Layer (solid, remove dead copper, pour order 12): 13115,8155 13300,8155 13960,8815 16235,8815 16695,8355 17162.66,8355 17162.66,8185 16480,8185 16270,8395 14085,8395 13420,7730 13325,7730 13325,7840 13120,8045 13120,8150
12VOUT on Top Layer (solid, remove dead copper, pour order 14): 17145,8602.11 17145,8437.25 17232.21,8350.04 17305.04,8350.04 17330,8375 17330,8601.32 17145.78,8601.32
GND on Inner2 (solid, remove dead copper): 19470,9565 20185,8850 20185,3600 19740,3155 11615,3155 11535,3075 11115,3495 11115,9315 11365,9565
GND on Inner1 (solid, remove dead copper): 19470,9565 20185,8850 20185,3600 19740,3155 11615,3155 11535,3075 11115,3495 11115,9315 11365,9565
GND on Bottom Layer (solid, remove dead copper, pour order 18): 19490,9540 20205,8825 20205,3575 19760,3130 11635,3130 11555,3050 11135,3470 11135,9290 11385,9540
GND on Top Layer (solid, remove dead copper, pour order 16): 19500,9490 20215,8775 20215,3525 19770,3080 11645,3080 11565,3000 11145,3420 11145,9240 11395,9490

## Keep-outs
Top Layer:
  region: 15905,8220 16115,8220 16115,5675 15905,5675
  region: 15550,4394.86 15660,4394.86 15660,3349.86 15550,3349.86
  region: 16617.99,4394.86 16727.99,4394.86 16727.99,3349.86 16617.99,3349.86
  region: 17545,5109.86 17655,5109.86 17655,4269.86 17545,4269.86
  region: 19250,5099.86 19360,5099.86 19360,4779.86 19250,4779.86
  region: 14105,8220 14315,8220 14315,5675 14105,5675
  region: 17164.82,8335 17185,8335 17200,8320 17200,8300 17205,8295 17163.81,8295 17163.81,8333.99
Board Outline Layer:
  lines w10: 11580,3339.49 19454.02,3339.49 19454.02,9245 11580,9245 11580,3339.49

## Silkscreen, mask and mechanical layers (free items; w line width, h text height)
Top Silkscreen Layer:
  lines w10: 18795,5585 18760,5550 ; 18797.46,5512.54 18760,5550 ; 19410,5875 19410,5605 19355,5550 18760,5550 ; 14105,5310.08 16122.32,5310.08 16122.32,8569.92 14105,8569.92 14105,5310.08
  text "D12V" at 18660,8715 h59.06 r90
  text "GND" at 18852.8,8715 h59.06 r90
  text "485_N" at 19045.6,8715 h59.06 r90
  text "485_P" at 19250,8715 h59.06 r90
  text "D12V" at 11760,8700 h59.06 r90
  text "GND" at 11952.8,8700 h59.06 r90
  text "485_N" at 12145.6,8700 h59.06 r90
  text "485_P" at 12350,8700 h59.06 r90
  text "D12V" at 12755,8695 h59.06 r90
  text "GND" at 12947.8,8695 h59.06 r90
  text "485_N" at 13140.6,8695 h59.06 r90
  text "485_P" at 13345,8695 h59.06 r90
  text "D12V" at 14725,8685 h59.06 r90
  text "GND" at 14917.8,8685 h59.06 r90
  text "485_N" at 15110.6,8685 h59.06 r90
  text "485_P" at 15315,8685 h59.06 r90
  text "D12V" at 13750,8680 h59.06 r90
  text "GND" at 13942.8,8680 h59.06 r90
  text "485_N" at 14135.6,8680 h59.06 r90
  text "485_P" at 14340,8680 h59.06 r90
  text "D12V" at 15710,8675 h59.06 r90
  text "GND" at 15902.8,8675 h59.06 r90
  text "485_N" at 16095.6,8675 h59.06 r90
  text "485_P" at 16300,8675 h59.06 r90
  text "D12V" at 16705,8670 h59.06 r90
  text "GND" at 16897.8,8670 h59.06 r90
  text "485_N" at 17090.6,8670 h59.06 r90
  text "485_P" at 17295,8670 h59.06 r90
  text "D12V" at 17700,8665 h59.06 r90
  text "GND" at 17892.8,8665 h59.06 r90
  text "485_N" at 18085.6,8665 h59.06 r90
  text "485_P" at 18290,8665 h59.06 r90
  text "D12V" at 18805,8555 h59.06
  text "GND" at 18805,8362.2 h59.06
  text "485_N" at 18805,8169.4 h59.06
  text "485_P" at 18805,7965 h59.06
  text "D12V" at 18795,7660 h59.06
  text "GND" at 18795,7467.2 h59.06
  text "485_N" at 18795,7274.4 h59.06
  text "485_P" at 18795,7070 h59.06
  text "bpm280" at 18215,5730 h59.06
  text "SDA3" at 18490,5730 h59.06
  text "SCL3" at 18490,5663.33 h59.06
  text "GND" at 18490,5596.67 h59.06
  text "3V3" at 18490,5530 h59.06
  text "RST" at 17555,5350 h59.06
  text "D5V0" at 17575,4005 h59.06
  text "RX" at 15415,3890 h59.06
  text "TX" at 15415.72,3805 h59.06
  text "SCL2_PF1" at 11815,3737.48 h59.06 r90
  text "SDA2_PF0" at 12010,3737.48 h59.06 r90
  text "IO_PE9" at 12435.15,3737.48 h59.06 r90
  text "IO_PE13" at 12625,3737.48 h59.06 r90
  text "IO_PE10" at 13035,3737.48 h59.06 r90
  text "IO_PF13" at 13246.11,3737.48 h59.06 r90
  text "IO_PE11" at 13650,3737.48 h59.06 r90
  text "IO_PE12" at 13851.64,3737.48 h59.06 r90
  text "IO_PE14" at 14281.64,3737.48 h59.06 r90
  text "IO_PE8" at 14480.96,3737.48 h59.06 r90
  text "UART5_TX_PC12" at 14891.64,3737.48 h59.06 r90
  text "UART5_RX_PD2" at 15090,3737.48 h59.06 r90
